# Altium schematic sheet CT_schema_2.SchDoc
size 143 x 108 mm
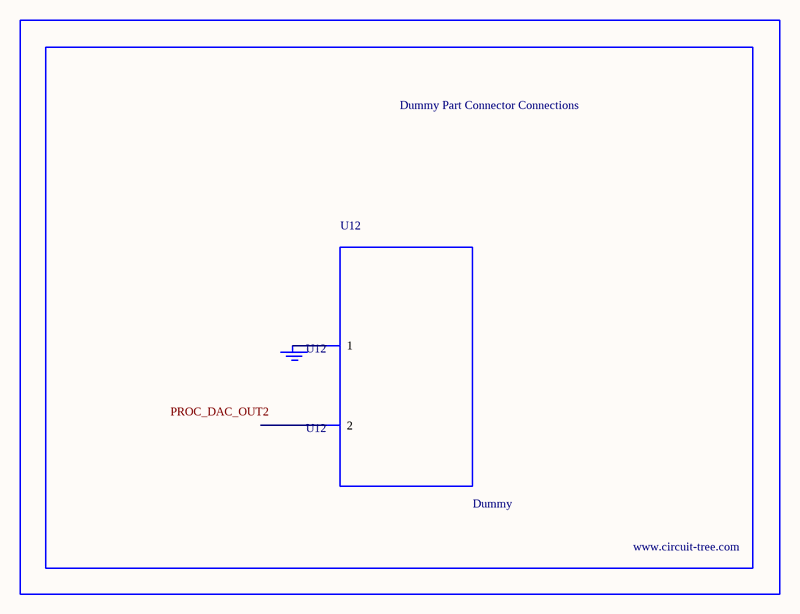
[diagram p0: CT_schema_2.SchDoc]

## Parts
BORDER1  (no value)
GND_INSTANCE_1_0  (no value)
U12  Dummy  [DUMMY_PACKAGE_92]

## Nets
NetGND_INSTANCE_1_0_0: GND_INSTANCE_1_0.0(GND) U12.1

Not connected (* = marked no-connect by the designer): U12 2

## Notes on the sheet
- Labels drawn without touching a wire or pin: PROC_DAC_OUT2

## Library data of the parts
BORDER1 = BORDER_PAGE1
GND_INSTANCE_1_0 = GND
